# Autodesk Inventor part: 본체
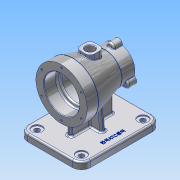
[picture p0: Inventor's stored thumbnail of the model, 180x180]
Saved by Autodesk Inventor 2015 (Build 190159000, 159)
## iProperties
Created: 2021-10
Part Number: 본체
Material: 알루미늄 6061
Document SubType Name: Modeling
Designer: 101256544
Density: 2.7 g/cm^3
Appearance: 알루미늄 - 평지
Mass: 1223.16 g
Surface Area: 900.075 cm^2
Volume: 453.022 cm^3
Author: 101256544
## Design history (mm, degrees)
sketch "스케치1"
  geometry: L1 (0, 77.575)-(0, -77.575); L2 (0, 50)-(45, 50); L3 (45, 50)-(45, 30); L4 (45, 30)-(29, -27); L5 (29, -27)-(29, -50); L6 (29, -50)-(0, -50); L7 (0, 50)-(0, -50); L8 (17.773, 50)-(17.773, -50); 3 further points
  constraints: 16 end point, 4 point on line, 3 perpendicular, 2 midpoint, 1 coincident, 1 collinear, 1 horizontal, 1 horizontal alignment, 1 parallel, 1 vertical
  dimensions: "d0" = 90 diameter of L3 L1; "d1" = 58 diameter of L5 L1; "d2" = 100 vertical distance of L5.end L2.end; "d3" = 20 distance of L2.end L3.end; "d4" = 23 distance of L4.end L5.end
revolve "회전1" sketch "스케치1" stored, may be unused: angle "d5" = 90 deg
sketch "스케치2"
  geometry: L1 (0, 68.61)-(0, -68.61); L2 (-45, 50)-(45, 50) reference; L3 (-29, -50)-(29, -50) reference; L4 (0, 50)-(31, 50); L5 (31, 50)-(31, 27); L6 (31, 27)-(0, 27); L7 (0, 27)-(0, 50); L8 (0, 27)-(25, 27); L9 (25, 27)-(25, -20); L10 (25, -20)-(0, -20); L11 (0, -20)-(0, 27); L12 (0, -20)-(19, -20); L13 (19, -20)-(19, -50); L14 (19, -50)-(0, -50); L15 (0, -50)-(0, -20); 2 further points
  constraints: 26 end point, 6 parallel, 3 horizontal, 3 perpendicular, 2 midpoint, 1 coincident, 1 point on line, 1 vertical
  dimensions: "d6" = 62 diameter of L5 L1; "d7" = 50 diameter of L9 L1; "d9" = 38 diameter of L13 L1; "d10" = 23 distance of L4.end L5.end; "d11" = 47 distance of L8.end L9.end
revolve "회전2" sketch "스케치2" stored, may be unused: angle "d12" = 90 deg
sketch "스케치3" dims "d13" = 80
  geometry: C1 r 31 at (0, 0) reference; C2 r 45 at (0, 0) reference; 2 further points
  constraints: 2 vertical alignment, 1 coincident, 2 other
hole "구멍1" sketch "스케치3" at (0, 40) diameter "d14" = 3.242; stored, may be unused: countersink angle "d18" = 90 deg, drill point angle "d20" = 118 deg; dims "d15" = 9, "d16" = 4, "d17" = 2, "d19" = 11
sketch "스케치4"
  geometry: C1 r 19 at (0, 0) reference; C2 r 7 at (0, 29); 2 further points
  constraints: 2 vertical alignment, 1 centre point, 1 coincident, 1 other
  dimensions: "d24" = 14 diameter of C2
extrude "돌출1" join sketch "스케치4" distance "d25" = 15; taper "d26" = 0 deg
hole "구멍2" sketch "스케치4" diameter "d27" = 3.242; stored, may be unused: countersink angle "d31" = 90 deg, drill point angle "d33" = 118 deg; dims "d28" = 9, "d29" = 4, "d30" = 2, "d32" = 11
node "작업 평면1"
sketch "스케치5"
  geometry: L1 (-45, 50)-(45, 50) reference; L2 (6.949, -50)-(29, -50) reference; L3 (55, 70)-(-55, 70); L4 (-55, 70)-(-55, -70); L5 (-55, -70)-(55, -70); L6 (55, -70)-(55, 70); 3 further points
  constraints: 8 end point, 2 parallel, 1 horizontal, 1 midpoint, 1 perpendicular, 1 vertical alignment
  dimensions: "d38" = 140 distance of L5.end L3.start; "d39" = 110 distance of L3.start L3.end; "d40" = 20 distance between parallel lines of L3 L1
extrude "돌출2" join sketch "스케치5" distance "d41" = 12; taper "d42" = 0 deg
sketch "스케치6"
  geometry: L1 (4, -37)-(-4, -37); L2 (-4, -37)-(-4, 37); L3 (-4, 37)-(4, 37); L4 (4, 37)-(4, -37); L5 (4, -37)-(-4, 37); L6 (-4, -37)-(4, 37); L7 (24, 4)-(-24, 4); L8 (-24, 4)-(-24, -4); L9 (-24, -4)-(24, -4); L10 (24, -4)-(24, 4); L11 (24, 4)-(-24, -4); L12 (-24, 4)-(24, -4); 1 further point
  constraints: 24 end point, 4 midpoint, 4 parallel, 2 horizontal, 2 perpendicular
  dimensions: "d43" = 8 distance of L7.end L8.end; "d44" = 8 distance of L2.end L3.end; "d45" = 74 distance of L3.end L1.start; "d46" = 24 distance from line of L8 point (0, 0); "d47" = 24 distance from line of L10 point (0, 0) (derived)
extrude "돌출3" join sketch "스케치6" stored distance "d48" = 12; taper "d49" = 0 deg
feature "면 기울기1" dims angle "d50" = 5 deg
feature "면 기울기2" dims angle "d51" = 5 deg
node "작업 평면2"
sketch "스케치7"
  geometry: L1 (-12.5, 12.5)-(12.5, 12.5); L2 (12.5, 12.5)-(12.5, -12.5); L3 (12.5, -12.5)-(-12.5, -12.5); L4 (-12.5, -12.5)-(-12.5, 12.5); L5 (-12.5, 12.5)-(12.5, -12.5); L6 (12.5, 12.5)-(-12.5, -12.5); 2 further points
  constraints: 12 end point, 2 midpoint, 2 parallel, 1 coincident, 1 horizontal, 1 perpendicular
  dimensions: "d53" = 25 distance of L2.end L3.end; "d54" = 25 distance of L1.end L2.end
extrude "돌출4" join sketch "스케치7" stored distance "d55" = 12; taper "d56" = 0 deg
hole "구멍3" sketch "스케치7" diameter "d57" = 15; stored, may be unused: countersink angle "d61" = 90 deg, drill point angle "d63" = 118 deg; dims "d58" = 9, "d59" = 4, "d60" = 2, "d62" = 30
chamfer "모따기1" distance "d64" = 1; stored, may be unused: second distance "d65" = 2, angle "d66" = 45 deg
fillet "모깎기1" dims "d67" = 3, "d68" = 16, "d69" = 8
fillet "모깎기2" dims "d70" = 3, "d71" = 1
sketch "스케치8"
  geometry: A1 r 13 centre (39, -54) between (39, -67) and (52, -54) reference; A2 r 13 centre (39, 54) between (52, 54) and (39, 67) reference; A3 r 13 centre (-39, 54) between (-39, 67) and (-52, 54) reference; A4 r 13 centre (-39, -54) between (-52, -54) and (-39, -67) reference; 5 further points
  constraints: 4 coincident
hole "구멍4" sketch "스케치8" at (-39, -54), (-39, 54), (39, -54), (39, 54) diameter "d72" = 9; stored, may be unused: countersink angle "d76" = 90 deg, drill point angle "d78" = 118 deg; dims "d73" = 9, "d74" = 18, "d75" = 2, "d77" = 10
sketch "스케치9"
  geometry: L1 (55, -54)-(55, 54) reference; 2 further points
  constraints: 1 horizontal alignment, 1 other
  dimensions: "d79" = 15 distance from line of L1 point (40, 0)
feature "엠보싱1" sketch "스케치9" dims "d0" = 90, "d1" = 58, "d2" = 100, "d3" = 20, "d4" = 23, "d6" = 62, "d7" = 50, "d9" = 38, "d10" = 23, "d11" = 47, "d80" = 0.5, "d81" = 0
fillet "모깎기3" dims "d82" = 3
node "솔리드1"
pattern_circular "원형 패턴1" dims angle "d22" = 360 deg
pattern_circular "원형 패턴2" dims angle "d35" = 360 deg
other parameters: "d37" = -82, "d52" = 45
